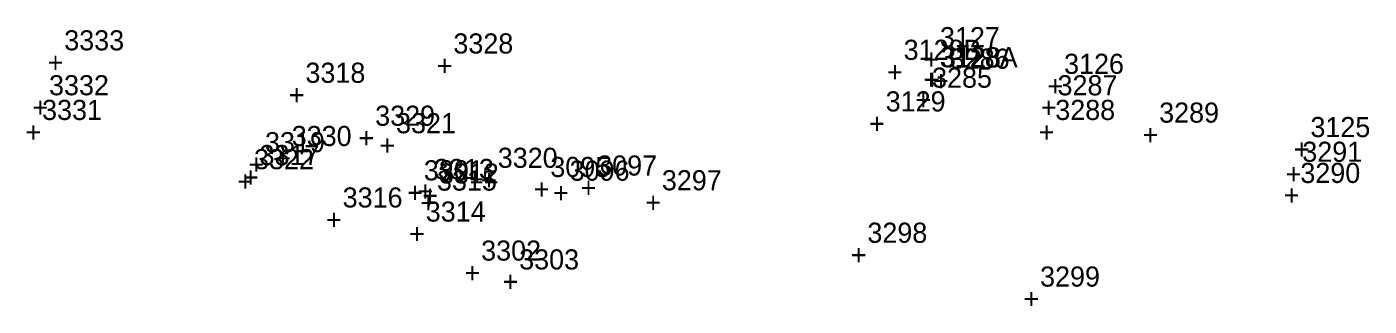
# Model space of a CAD drawing. Extents: x 1136220 to 1137808, y 528804 to 531215.
# Drawn here: x 1136811.6 to 1136978.3, y 529853.4 to 529888.1 of the extents above; entities that cross this region are included whole.
import ezdxf

# ---------------------------------------------------------------- set-up
doc = ezdxf.new("R2010")
doc.units = 0
for name, color, linetype in [('S_Drainage_CB', 7, 'Continuous'), ('S_Drainage_Culvert_Top', 7, 'Continuous'), ('S_Drainage_Invert', 7, 'Continuous'), ('S_Drainage_Sump', 7, 'Continuous'), ('S_Ground_Elevation', 7, 'Continuous'), ('S_Railroad_Signal', 7, 'Continuous'), ('S_Railroad_Tracks', 7, 'Continuous'), ('S_Roadway_Centerline', 7, 'Continuous'), ('S_Roadway_Edge_Pavement', 7, 'Continuous'), ('S_Utilities_UG_Sanitary_MH', 7, 'Continuous'), ('S_Utilities_UG_Water_Gate', 7, 'Continuous')]:
    doc.layers.add(name, color=color, linetype=linetype)

msp = doc.modelspace()

# ---------------------------------------------------------------- texts
at = {"layer": 'S_Drainage_CB'}
for s, p in [('3317', (1136840.47, 529870.91)), ('+', (1136838.41, 529868.16)), ('3312', (1136862.74, 529868.63)), ('+', (1136860.67, 529865.88))]:
    msp.add_text(s, height=2.5, dxfattribs=at).set_placement(p)
at = {"layer": 'S_Drainage_Culvert_Top'}
for s, p in [('3128B', (1136920.45, 529883.99)), ('3128A', (1136924.94, 529883.07)), ('3318', (1136846.17, 529881.14)), ('+', (1136918.39, 529881.24)), ('+', (1136922.88, 529880.32)), ('+', (1136844.11, 529878.39)), ('3314', (1136861.11, 529863.89)), ('+', (1136859.05, 529861.14))]:
    msp.add_text(s, height=2.5, dxfattribs=at).set_placement(p)
at = {"layer": 'S_Drainage_Invert'}
for s, p in [('3128', (1136925.09, 529883.04)), ('+', (1136923.03, 529880.29)), ('3319', (1136841.15, 529872.51)), ('+', (1136839.09, 529869.76)), ('3315', (1136862.5, 529867.74)), ('+', (1136860.44, 529864.99))]:
    msp.add_text(s, height=2.5, dxfattribs=at).set_placement(p)
at = {"layer": 'S_Drainage_Sump'}
for s, p in [('3313', (1136862.14, 529869.18)), ('+', (1136860.08, 529866.43))]:
    msp.add_text(s, height=2.5, dxfattribs=at).set_placement(p)
at = {"layer": 'S_Ground_Elevation'}
for s, p in [('3333', (1136816.22, 529885.17)), ('3127', (1136924.96, 529885.56)), ('3286', (1136926.17, 529882.89)), ('+', (1136814.16, 529882.42)), ('+', (1136922.9, 529882.81)), ('3126', (1136940.37, 529882.25)), ('3332', (1136814.33, 529879.59)), ('3285', (1136923.98, 529880.53)), ('+', (1136924.1, 529880.14)), ('3287', (1136939.56, 529879.58)), ('+', (1136938.31, 529879.5)), ('+', (1136812.27, 529876.84)), ('3329', (1136854.83, 529875.8)), ('+', (1136921.92, 529877.78)), ('+', (1136937.49, 529876.83)), ('3288', (1136939.28, 529876.52)), ('3125', (1136970.96, 529874.39)), ('3330', (1136844.47, 529873.28)), ('+', (1136852.76, 529873.05)), ('+', (1136937.22, 529873.77)), ('+', (1136968.9, 529871.64)), ('3291', (1136969.95, 529871.32)), ('+', (1136842.41, 529870.53)), ('+', (1136967.89, 529868.57)), ('3290', (1136969.71, 529868.69)), ('+', (1136967.65, 529865.94))]:
    msp.add_text(s, height=2.5, dxfattribs=at).set_placement(p)
at = {"layer": 'S_Railroad_Signal'}
for s, p in [('3301', (1136860.87, 529869.01)), ('+', (1136858.81, 529866.26))]:
    msp.add_text(s, height=2.5, dxfattribs=at).set_placement(p)
at = {"layer": 'S_Railroad_Tracks'}
for s, p in [('3302', (1136867.99, 529859.04)), ('3303', (1136872.71, 529857.94)), ('+', (1136865.93, 529856.29)), ('+', (1136870.65, 529855.19))]:
    msp.add_text(s, height=2.5, dxfattribs=at).set_placement(p)
at = {"layer": 'S_Roadway_Centerline'}
for s, p in [('3328', (1136864.54, 529884.78)), ('+', (1136862.48, 529882.03))]:
    msp.add_text(s, height=2.5, dxfattribs=at).set_placement(p)
at = {"layer": 'S_Roadway_Edge_Pavement'}
for s, p in [('3331', (1136813.47, 529876.52)), ('3321', (1136857.42, 529874.87)), ('+', (1136811.41, 529873.77)), ('+', (1136855.36, 529872.12)), ('3322', (1136839.79, 529870.4)), ('3320', (1136870.05, 529870.57)), ('3095', (1136876.58, 529869.43)), ('3097', (1136882.4, 529869.61)), ('3096', (1136878.98, 529868.97)), ('3297', (1136890.43, 529867.78)), ('+', (1136837.72, 529867.65)), ('+', (1136867.99, 529867.82)), ('+', (1136874.52, 529866.68)), ('+', (1136876.92, 529866.22)), ('+', (1136880.34, 529866.86)), ('+', (1136888.37, 529865.03)), ('3298', (1136915.95, 529861.26)), ('+', (1136913.89, 529858.51)), ('3299', (1136937.39, 529855.81)), ('+', (1136935.33, 529853.06))]:
    msp.add_text(s, height=2.5, dxfattribs=at).set_placement(p)
at = {"layer": 'S_Utilities_UG_Sanitary_MH'}
for s, p in [('3129', (1136918.22, 529877.58)), ('+', (1136916.16, 529874.83))]:
    msp.add_text(s, height=2.5, dxfattribs=at).set_placement(p)
at = {"layer": 'S_Utilities_UG_Water_Gate'}
for s, p in [('3289', (1136952.18, 529876.19)), ('+', (1136950.12, 529873.44)), ('3316', (1136850.79, 529865.64)), ('+', (1136848.73, 529862.89))]:
    msp.add_text(s, height=2.5, dxfattribs=at).set_placement(p)

doc.saveas('drawing.dxf')
